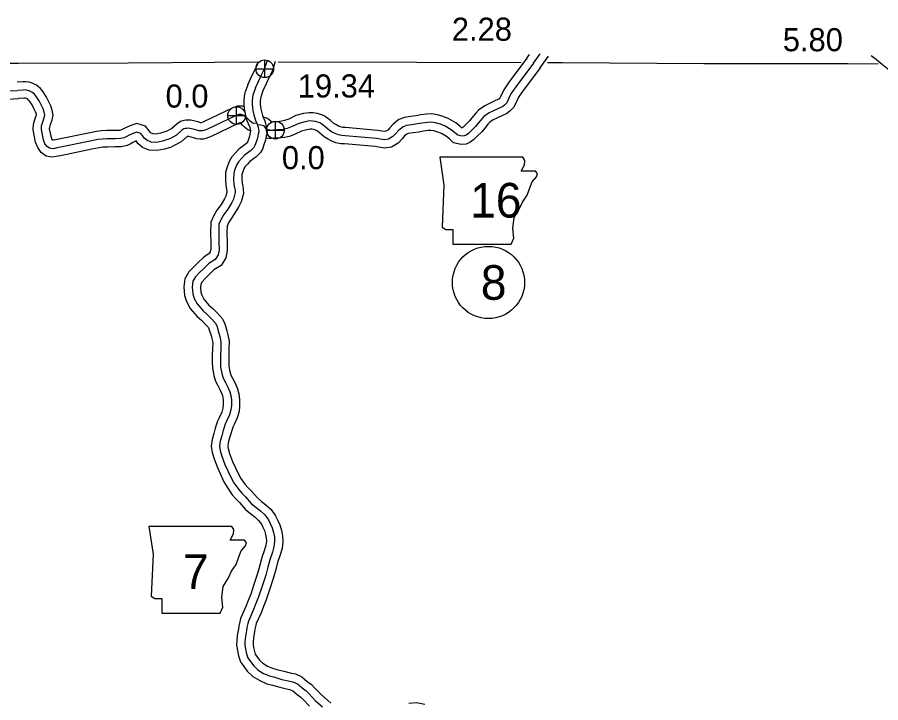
# Model space of a CAD drawing. Extents: x 31699 to 244310, y -8841 to 11474.
# Drawn here: x 96581 to 97635, y 8769 to 9604 of the extents above; entities that cross this region are included whole.
import ezdxf

# ---------------------------------------------------------------- set-up
doc = ezdxf.new("R2010")
doc.units = 0
for name, color, linetype in [('B_Logo', 7, 'Continuous'), ('G-ANNO-TEXT', 7, 'Continuous'), ('Level 21', 7, 'Continuous'), ('R_Border Notes', 7, 'Continuous'), ('R_Logo', 7, 'Continuous'), ('R_XS_EARTHWORK_STAGE2', 7, 'Continuous'), ('S_WALL_ANNOT', 7, 'Continuous')]:
    doc.layers.add(name, color=color, linetype=linetype)

msp = doc.modelspace()

# ---------------------------------------------------------------- linework, layer by layer
at = {"layer": 'B_Logo'}
for points in [[(97211.2, 9548.6), (97219.5, 9559.9)], [(96871.9, 9518.4), (96875.1, 9525.2), (96879.1, 9533.6), (96882.6, 9540.9), (96884.6, 9545.9), (96886.2, 9550.9), (96886.5, 9552)], [(97211.2, 9548.6), (97189.6, 9519.7), (97185.7, 9513.9), (97183.6, 9510.9), (97181.2, 9505.6), (97178.6, 9500.3), (97175.9, 9497.3), (97173.6, 9495.7), (97167.5, 9492.9), (97157, 9487.9), (97150.8, 9483.6), (97148.4, 9481), (97143.9, 9475.5), (97140.6, 9471.3), (97135.5, 9466.3), (97132.1, 9462.8), (97128.9, 9460.5), (97126.7, 9459.7), (97123.6, 9459.3), (97118.7, 9460.6), (97115.2, 9463.7), (97110.8, 9467.3), (97103.3, 9471.6), (97097.8, 9474), (97091.7, 9475.6), (97086.5, 9476.5), (97081.7, 9476.3), (97075.3, 9475.4), (97069.7, 9474.4), (97062.8, 9473.4), (97056.2, 9472.4), (97052, 9471), (97046.9, 9466.9), (97043.3, 9462.8), (97039.7, 9459), (97034.4, 9455.8), (97029.1, 9455), (97019.5, 9456.6), (96981.3, 9460), (96977.3, 9460.2), (96973.1, 9461.1), (96969.2, 9462.6), (96964.9, 9464.8), (96961.8, 9466.8), (96956.6, 9471.2), (96953, 9474.2), (96950.5, 9475.6), (96945.4, 9477.4), (96941.5, 9477.9), (96938.2, 9478), (96932.5, 9477.1), (96924.8, 9475.1), (96916.6, 9471.1), (96910.6, 9468.8), (96905.8, 9467.7), (96899, 9467.1), (96893.8, 9466.8), (96890.9, 9466.5), (96889.8, 9466.6), (96887.1, 9467), (96885.1, 9468.5), (96883.4, 9470.7), (96882, 9472), (96878.6, 9472.9), (96874.5, 9473.4)], [(96534.7, 9516.4), (96538.7, 9517.3), (96542.4, 9517.2), (96545.6, 9517.2), (96550.5, 9516.7), (96556.5, 9516.1), (96562.1, 9515.5), (96564.7, 9515.2), (96570.1, 9514.6), (96582, 9515.3)], [(96873.7, 9475.2), (96870.2, 9475), (96867.8, 9475.9), (96865.5, 9477.9), (96863, 9480.2), (96861.4, 9481.8), (96859.7, 9483.5), (96857.9, 9484.8), (96854.5, 9486), (96851.8, 9486), (96847.7, 9484.3), (96813.4, 9468.1), (96811.3, 9467.3), (96808.5, 9466.2), (96807.1, 9465.9), (96805, 9465.8), (96802.7, 9466.1), (96799.1, 9467.2), (96795.9, 9468.1), (96791.9, 9468.9), (96790, 9469.1), (96788.2, 9468.9), (96786.4, 9468.8), (96784.8, 9468.3), (96782.3, 9466.6), (96775.6, 9460.8), (96768.5, 9456.8), (96764.8, 9455.2), (96758.7, 9453.5), (96751.2, 9451.9), (96744.8, 9452.2), (96739.5, 9454.4), (96736.2, 9457.2), (96734.3, 9460.2), (96732, 9462.9), (96727.3, 9464.4), (96723.5, 9463.2), (96717.9, 9460.6), (96714.2, 9458.7), (96712, 9457.5), (96707.3, 9456.6), (96700.8, 9456.3), (96691, 9456.2), (96685.1, 9455.8), (96679.5, 9455.3), (96670.3, 9453.4), (96634.1, 9445.9), (96629.7, 9445.1), (96627.1, 9444.6), (96623.8, 9444.1), (96620.7, 9444.7), (96617.7, 9446.8), (96615.2, 9450.2), (96613.4, 9455), (96610.8, 9467.7), (96611.1, 9472.2), (96612.5, 9476.8), (96614.3, 9482), (96615, 9485.3), (96614.4, 9488.8), (96613, 9492.7), (96611, 9497), (96608, 9502.6), (96604.9, 9507.5), (96602.4, 9510.5), (96599.3, 9513.3), (96596.1, 9514.7), (96593.9, 9515.3), (96591.1, 9515.8), (96588.7, 9515.7), (96582, 9515.3)], [(96871.9, 9518.4), (96868.8, 9509.6), (96868.3, 9507), (96867.9, 9502.3), (96867.9, 9498.5), (96868.3, 9493.9), (96868.8, 9490.8), (96870, 9485.5), (96871.1, 9481.6), (96872.2, 9478.5), (96873.7, 9475.2), (96874.5, 9473.4), (96875.7, 9468.1), (96876.1, 9464.6), (96875.2, 9461.8), (96874.5, 9457), (96873.3, 9453.5), (96871.3, 9447.9), (96870.1, 9445.8), (96865.9, 9441.6), (96858.5, 9436.1), (96854.9, 9432.2), (96851.4, 9428.3), (96848.9, 9424.2), (96846.5, 9417.9), (96845.5, 9413.9), (96845.3, 9406.6), (96845.7, 9400.9), (96846.6, 9396.6), (96847.2, 9393.4), (96847.3, 9390.7), (96845.2, 9382.8), (96843.1, 9378.4), (96838.3, 9370.6), (96833.4, 9363.8), (96830.3, 9358.3), (96827.5, 9352.1), (96827.1, 9341.8), (96827.5, 9329.8), (96827.6, 9320.9), (96826.3, 9314.9), (96822.7, 9308.9), (96815.1, 9304.2), (96809, 9298.3), (96803.4, 9292.8), (96798.7, 9287.9), (96795.6, 9282.5), (96794.7, 9275.4), (96795.5, 9267.3), (96797.2, 9261.6), (96800.7, 9255.1), (96808.1, 9246.5), (96813.2, 9242), (96818.4, 9236.9), (96823.2, 9231.4), (96825.1, 9227), (96827.4, 9219.4), (96828.7, 9215.1), (96829.8, 9208.6), (96829.6, 9200.2), (96829.3, 9191.8), (96829.3, 9184.2), (96829.4, 9178), (96830.8, 9170.2), (96832.7, 9164.4), (96835, 9159.9), (96838, 9154.2), (96840.6, 9147.8), (96842.1, 9143.1), (96842.7, 9137.9), (96842.7, 9131.1), (96842.1, 9125.9), (96840.2, 9119.6), (96836.8, 9112.1), (96835.1, 9108.2), (96832.6, 9100.6), (96830.8, 9094.2), (96829, 9087.5), (96828, 9081.5), (96828.8, 9076.1), (96831.1, 9069.4), (96834.8, 9059.1), (96842.4, 9042.7), (96845.8, 9036.9), (96851.5, 9028.5), (96855.4, 9024.1), (96859.8, 9019.7), (96866.9, 9011.6), (96872.7, 9006.8), (96878.2, 9002.5), (96883.4, 8997.7), (96887.7, 8991.5), (96890, 8987.2), (96892.2, 8982), (96894.1, 8976.1), (96895.1, 8971), (96895.4, 8965.4), (96894.6, 8958.8), (96892.8, 8952.1), (96889.4, 8942.8), (96887.1, 8933.9)], [(96887.1, 8933.9), (96884.6, 8924.4), (96880, 8910.9), (96875.6, 8897.6), (96872.5, 8889.8), (96869.6, 8882.3), (96863.3, 8868.3), (96862.7, 8865.3), (96861.6, 8860.5), (96860.9, 8856.9), (96859.7, 8849.3), (96859.1, 8843), (96859, 8839.4), (96859.8, 8834), (96861, 8828.5), (96862.7, 8823.3), (96869.5, 8813.9), (96874.9, 8808.8), (96882, 8804.5), (96889.3, 8801.3), (96895.5, 8799.7), (96904.2, 8797.2), (96912, 8795.5), (96917.4, 8794.3), (96923.1, 8791.7), (96928.9, 8786.7), (96933.7, 8783.2), (96937.5, 8779.5), (96945, 8771.6), (96953.7, 8763.8)]]:
    msp.add_lwpolyline(points, dxfattribs=at)
at = {"layer": 'G-ANNO-TEXT'}
for points in [[(97097, 9433.7), (97102, 9399.9), (97099.8, 9348.6), (97104.3, 9345.7), (97112.7, 9345.7), (97112.7, 9327.7), (97183.8, 9327.7), (97187.2, 9335), (97186.1, 9346.9), (97187.8, 9360.4), (97194, 9371.1), (97197.9, 9379), (97203.5, 9387.5), (97206.9, 9396.5), (97209.7, 9403.8), (97214.8, 9410), (97215.9, 9414), (97213.7, 9416.8), (97196.2, 9416.8), (97200.2, 9424.7), (97200.7, 9429.8), (97198.4, 9433.7)], [(96741.9, 8983.7), (96747, 8949.8), (96744.7, 8898.5), (96749.2, 8895.7), (96757.7, 8895.7), (96757.7, 8877.7), (96828.8, 8877.7), (96832.1, 8885), (96831, 8896.8), (96832.7, 8910.4), (96838.9, 8921.1), (96842.9, 8929), (96848.5, 8937.4), (96851.9, 8946.5), (96854.7, 8953.8), (96859.8, 8960), (96860.9, 8963.9), (96858.6, 8966.8), (96841.2, 8966.8), (96845.1, 8974.7), (96845.7, 8979.7), (96843.3, 8983.6)]]:
    msp.add_lwpolyline(points, close=True, dxfattribs=at)
at = {"layer": 'Level 21'}
for p, q in [((96883.3, 9530.8), (96883.3, 9552.5)), ((96872.4, 9541.6), (96894.1, 9541.6)), ((96849, 9473.7), (96849, 9495.4)), ((96838.1, 9484.5), (96859.8, 9484.5)), ((96896.4, 9456), (96896.4, 9477.7)), ((96885.6, 9466.8), (96907.3, 9466.8))]:
    msp.add_line(p, q, dxfattribs=at)
for centre in [(96883.3, 9541.6), (96849, 9484.5), (96896.4, 9466.8)]:
    msp.add_circle(centre, 10.8, dxfattribs=at)
at = {"layer": 'R_Border Notes'}
msp.add_circle((97156.3, 9281.1), 44, dxfattribs=at)
at = {"layer": 'R_Logo'}
for points in [[(96089.4, 9556.1), (96192.5, 9555.3), (96361.7, 9545.8), (96371.2, 9545.5), (96540.1, 9548.2), (96548.3, 9548.3), (96582.7, 9548.4)], [(96582.7, 9548.4), (96716.8, 9548.7), (96875, 9550)], [(96899.7, 9550.2), (97069, 9549.5), (97196, 9549.4)], [(97228.3, 9549.3), (97246.7, 9549.3), (97419.1, 9548), (97594.6, 9548.2), (97596.3, 9547.8), (97631.7, 9547.9)]]:
    msp.add_lwpolyline(points, dxfattribs=at)
at = {"layer": 'R_XS_EARTHWORK_STAGE2'}
for points in [[(97203.1, 9554.6), (97206.3, 9558.9)], [(97219.2, 9542.7), (97229.7, 9556.9)], [(97623.2, 9558), (97629.2, 9553.3), (97632.6, 9550.6), (97637.1, 9546.7), (97641.2, 9543.5), (97645, 9540.4), (97647.4, 9538.3), (97649.1, 9536.1), (97652.1, 9531.9), (97655.6, 9527.1), (97660.4, 9522.8), (97664.6, 9519.3), (97668.5, 9517.1), (97674.4, 9514.4), (97678.7, 9513.2), (97683.7, 9511.8)], [(96862.6, 9522.2), (96866.1, 9529.5), (96870, 9537.9), (96873.5, 9544.9), (96875.1, 9549.2), (96875.6, 9550.6)], [(96881.1, 9514.6), (96884.2, 9520.9), (96888.1, 9529.2), (96891.8, 9536.9), (96894, 9542.5), (96895.7, 9547.9), (96896.6, 9550.8)], [(97203.1, 9554.6), (97181.5, 9525.5), (97177.4, 9519.5), (97174.9, 9515.8), (97172.2, 9509.8), (97170.3, 9506), (97169.2, 9504.8), (97168.6, 9504.4), (97163.3, 9502), (97152, 9496.6), (97144.3, 9491.2), (97140.8, 9487.6), (97136.1, 9481.7), (97133.1, 9478), (97128.4, 9473.4), (97125.5, 9470.4), (97124.2, 9469.5), (97123.5, 9469.7), (97121.7, 9471.3), (97116.5, 9475.6), (97107.8, 9480.6), (97101.1, 9483.4), (97093.9, 9485.4), (97087.2, 9486.5), (97080.7, 9486.3), (97073.7, 9485.3), (97068.1, 9484.3), (97061.3, 9483.3), (97053.9, 9482.1), (97047.1, 9479.9), (97039.9, 9474.2), (97035.9, 9469.5), (97033.4, 9466.8), (97031, 9465.4), (97029.2, 9465.2), (97020.7, 9466.5), (96982, 9469.9), (96978.7, 9470.1), (96975.9, 9470.8), (96973.2, 9471.7), (96969.9, 9473.5), (96967.8, 9474.8), (96963, 9478.8), (96958.8, 9482.4), (96954.8, 9484.7), (96947.7, 9487.2), (96942.3, 9487.9), (96937.5, 9488), (96930.4, 9486.9), (96921.3, 9484.5), (96912.6, 9480.3), (96907.6, 9478.4), (96904.2, 9477.6), (96898.3, 9477.1), (96893, 9476.8), (96891.5, 9476.7), (96890.7, 9477.7), (96886.8, 9481), (96881.7, 9482.5)], [(97219.2, 9542.7), (97197.8, 9513.9), (97193.9, 9508.2), (97192.4, 9506), (97190.3, 9501.3), (97187, 9494.5), (97182.5, 9489.8), (97178.7, 9487), (97171.7, 9483.8), (97162.1, 9479.3), (97157.4, 9476), (97155.9, 9474.4), (97151.7, 9469.3), (97148, 9464.6), (97142.6, 9459.3), (97138.6, 9455.2), (97133.7, 9451.6), (97129.1, 9449.9), (97122.9, 9449.2), (97113.8, 9451.5), (97108.6, 9456.1), (97105.1, 9459.1), (97098.8, 9462.7), (97094.5, 9464.5), (97089.6, 9465.9), (97085.9, 9466.5), (97082.6, 9466.4), (97076.9, 9465.5), (97071.3, 9464.5), (97064.3, 9463.5), (97058.5, 9462.6), (97056.8, 9462), (97053.9, 9459.7), (97050.8, 9456.1), (97046.1, 9451.1), (97037.8, 9446.1), (97029, 9444.9), (97018.2, 9446.7), (96980.6, 9450), (96976, 9450.3), (96970.2, 9451.5), (96965.2, 9453.4), (96959.9, 9456.1), (96955.9, 9458.7), (96950.2, 9463.5), (96947.2, 9466), (96946.3, 9466.5), (96943.1, 9467.7), (96940.8, 9467.9), (96938.9, 9468), (96934.6, 9467.3), (96928.3, 9465.6), (96920.5, 9461.9), (96913.5, 9459.2), (96907.4, 9457.8), (96899.7, 9457.1), (96894.6, 9456.9), (96891.1, 9456.5), (96888.9, 9456.6), (96885.8, 9457.1)], [(96858.2, 9495.3), (96856.2, 9496), (96849.8, 9496), (96843.7, 9493.5), (96809.6, 9477.3), (96807.8, 9476.7), (96805.7, 9475.8), (96805.6, 9475.8), (96804.8, 9475.9), (96801.9, 9476.9), (96798.2, 9477.8), (96793.3, 9478.9), (96789.9, 9479.1), (96787.4, 9478.9), (96784.5, 9478.6), (96780.6, 9477.4), (96776.3, 9474.6), (96769.8, 9469), (96764, 9465.7), (96761.4, 9464.6), (96756.3, 9463.2), (96750.4, 9461.9), (96747, 9462.1), (96744.7, 9463.1), (96743.8, 9463.8), (96742.4, 9466.1), (96737.8, 9471.5), (96727.4, 9474.9), (96719.9, 9472.6), (96713.5, 9469.6), (96709.5, 9467.5), (96708.5, 9467), (96706.2, 9466.5), (96700.5, 9466.3), (96690.7, 9466.2), (96684.2, 9465.8), (96678, 9465.1), (96668.3, 9463.2), (96632.2, 9455.7), (96628, 9454.9), (96625.5, 9454.5), (96624.5, 9454.4), (96624.1, 9455), (96623, 9457.8), (96620.8, 9468.4), (96621, 9470.4), (96622, 9473.7), (96623.9, 9479.3), (96625.1, 9485.1), (96624.1, 9491.3), (96622.3, 9496.5), (96620, 9501.4), (96616.7, 9507.7), (96613, 9513.4), (96609.6, 9517.5), (96604.8, 9521.7), (96599.6, 9524.1), (96596.1, 9525.1), (96591.8, 9525.9), (96588.2, 9525.7), (96581.4, 9525.3)], [(96862.6, 9522.2), (96859.2, 9512.3), (96858.3, 9508.4), (96857.9, 9502.7), (96857.9, 9498.1), (96858.3, 9492.6), (96859, 9488.8), (96860.3, 9483.1), (96861.6, 9478.7), (96862.9, 9474.8), (96864.6, 9471.1), (96865, 9470.2), (96865.9, 9466.4), (96866, 9465.6), (96865.5, 9464), (96864.7, 9459.4), (96863.9, 9456.7), (96862.2, 9452), (96862.1, 9451.9), (96859.3, 9449.2), (96851.9, 9443.6), (96847.5, 9439), (96843.3, 9434.3), (96839.9, 9428.6), (96836.9, 9420.9), (96835.5, 9415.3), (96835.3, 9406.4), (96835.8, 9399.5), (96836.8, 9394.7), (96837.2, 9392.2), (96837.2, 9391.7), (96835.8, 9386.3), (96834.3, 9383.2), (96830, 9376.1), (96824.9, 9369.2), (96821.4, 9362.8), (96817.5, 9354.5), (96817.1, 9341.8), (96817.5, 9329.6), (96817.6, 9321.9), (96816.9, 9318.6), (96815.4, 9316.2), (96808.9, 9312.1), (96802, 9305.5), (96796.2, 9299.8), (96790.6, 9293.9), (96786, 9285.7), (96784.6, 9275.6), (96785.6, 9265.3), (96787.9, 9257.8), (96792.4, 9249.4), (96800.9, 9239.4), (96806.4, 9234.6), (96811.2, 9230), (96814.6, 9226), (96815.7, 9223.5), (96817.8, 9216.6), (96818.9, 9212.9), (96819.8, 9207.8), (96819.6, 9200.5), (96819.3, 9192), (96819.3, 9184.1), (96819.4, 9176.9), (96821.1, 9167.8), (96823.4, 9160.6), (96826.1, 9155.3), (96828.9, 9149.9), (96831.2, 9144.4), (96832.3, 9141), (96832.7, 9137.4), (96832.7, 9131.7), (96832.3, 9127.8), (96830.8, 9123.1), (96827.7, 9116.2), (96825.7, 9111.8), (96823, 9103.5), (96821.1, 9096.9), (96819.2, 9089.6), (96817.9, 9081.6), (96819, 9073.8), (96821.7, 9066.1), (96825.6, 9055.3), (96833.6, 9038.1), (96837.4, 9031.6), (96843.6, 9022.3), (96848.2, 9017.2), (96852.5, 9012.9), (96859.9, 9004.4), (96866.5, 8999), (96871.7, 8994.9), (96875.9, 8991), (96879.2, 8986.3), (96881, 8982.9), (96882.9, 8978.5), (96884.4, 8973.6), (96885.1, 8969.8), (96885.3, 8965.8), (96884.8, 8960.7), (96883.2, 8955.2), (96879.9, 8945.7), (96877.4, 8936.4)], [(96881.1, 9514.6), (96878.5, 9506.9), (96878.2, 9505.5), (96877.9, 9501.9), (96877.9, 9498.9), (96878.2, 9495.2), (96878.6, 9492.8), (96879.7, 9488), (96880.7, 9484.5), (96881.5, 9482.2), (96882.9, 9479.2), (96884, 9476.5), (96885.6, 9469.8), (96886.3, 9463.6), (96885, 9459.5), (96884.2, 9454.7), (96882.8, 9450.2), (96880.5, 9443.8), (96878.2, 9439.6), (96872.4, 9434), (96865.2, 9428.6), (96862.2, 9425.4), (96859.4, 9422.4), (96857.9, 9419.8), (96856, 9414.9), (96855.4, 9412.5), (96855.3, 9406.9), (96855.7, 9402.3), (96856.4, 9398.4), (96857.1, 9394.6), (96857.4, 9389.7), (96854.6, 9379.3), (96851.9, 9373.6), (96846.6, 9365), (96841.8, 9358.4), (96839.2, 9353.7), (96837.4, 9349.7), (96837.1, 9341.8), (96837.5, 9330), (96837.6, 9320), (96835.8, 9311.1), (96830, 9301.7), (96821.3, 9296.3), (96816, 9291.1), (96810.5, 9285.8), (96806.8, 9281.8), (96805.3, 9279.2), (96804.8, 9275.2), (96805.3, 9269.2), (96806.5, 9265.5), (96809, 9260.8), (96815.2, 9253.5), (96820, 9249.3), (96825.7, 9243.8), (96831.7, 9236.8), (96834.5, 9230.5), (96837, 9222.3), (96838.4, 9217.4), (96839.8, 9209.4), (96839.6, 9199.9), (96839.3, 9191.6), (96839.3, 9184.2), (96839.4, 9179), (96840.6, 9172.7), (96842, 9168.2), (96843.9, 9164.5), (96847.1, 9158.4), (96850, 9151.2), (96851.9, 9145.2), (96852.7, 9138.4), (96852.6, 9130.6), (96852, 9123.9), (96849.6, 9116), (96845.9, 9108), (96844.4, 9104.6), (96842.2, 9097.7), (96840.4, 9091.5), (96838.8, 9085.5), (96838.1, 9081.4), (96838.5, 9078.5), (96840.5, 9072.7), (96844.1, 9062.9), (96851.3, 9047.3), (96854.3, 9042.2), (96859.4, 9034.7), (96862.7, 9031), (96867.1, 9026.5), (96873.9, 9018.8), (96879, 9014.6), (96884.7, 9010.1), (96891, 9004.3), (96896.3, 8996.7), (96899, 8991.5), (96901.6, 8985.5), (96903.8, 8978.6), (96905.1, 8972.2), (96905.4, 8965.1), (96904.5, 8956.9), (96902.3, 8949.1), (96899, 8939.8), (96896.7, 8931.3)], [(96537, 9506.7), (96539.7, 9507.3), (96542.2, 9507.2), (96545, 9507.2), (96549.5, 9506.7), (96555.5, 9506.2), (96560.9, 9505.6), (96563.5, 9505.3), (96569.9, 9504.5), (96582.7, 9505.4)], [(96866, 9465.9), (96862.6, 9467.2), (96858.7, 9470.5), (96856.1, 9473), (96854.4, 9474.7), (96853.3, 9475.8), (96851.8, 9475.2), (96817.3, 9458.8), (96814.8, 9457.9), (96811.6, 9456.7), (96808.4, 9455.9), (96804.3, 9455.8), (96800.5, 9456.3), (96796.4, 9457.6), (96793.5, 9458.3), (96790.5, 9459), (96790.1, 9459), (96789.1, 9458.9), (96788.8, 9458.9), (96788.3, 9458.6), (96781.4, 9452.6), (96773, 9447.9), (96768.2, 9445.7), (96761.1, 9443.8), (96752, 9441.8), (96742.5, 9442.3), (96734.3, 9445.7), (96728.5, 9450.5), (96726.6, 9453.6), (96722.3, 9451.7), (96719, 9449.9), (96715.4, 9448), (96708.5, 9446.6), (96701, 9446.3), (96691.4, 9446.2), (96685.9, 9445.9), (96681.1, 9445.4), (96672.3, 9443.6), (96636, 9436), (96631.3, 9435.2), (96628.7, 9434.8), (96623.7, 9434), (96616.8, 9435.2), (96610.6, 9439.6), (96606.3, 9445.5), (96603.7, 9452.3), (96600.7, 9467), (96601.1, 9474), (96603, 9479.9), (96604.6, 9484.7), (96604.8, 9485.6), (96604.7, 9486.3), (96603.7, 9489), (96602.1, 9492.5), (96599.4, 9497.6), (96596.8, 9501.6), (96595.2, 9503.5), (96593.8, 9504.8), (96592.7, 9505.3), (96591.6, 9505.6), (96590.4, 9505.8), (96589.2, 9505.8), (96582.6, 9505.3)], [(96877.4, 8936.4), (96875, 8927.3), (96870.5, 8914.1), (96866.2, 8901), (96863.2, 8893.5), (96860.4, 8886.1), (96853.7, 8871.4), (96852.9, 8867.4), (96851.8, 8862.5), (96851.1, 8858.7), (96849.7, 8850.5), (96849.1, 8843.6), (96848.9, 8838.9), (96849.9, 8832.2), (96851.4, 8825.8), (96853.7, 8818.7), (96861.9, 8807.3), (96868.8, 8800.8), (96877.4, 8795.6), (96886, 8791.9), (96892.9, 8790), (96901.8, 8787.5), (96909.8, 8785.8), (96914.1, 8784.8), (96917.7, 8783.1), (96922.7, 8778.9), (96927.2, 8775.6), (96930.3, 8772.5), (96938, 8764.4)], [(96896.7, 8931.3), (96894.2, 8921.5), (96889.5, 8907.7), (96885, 8894.2), (96881.8, 8886.2), (96878.8, 8878.4), (96872.9, 8865.2), (96872.4, 8863.2), (96871.4, 8858.4), (96870.7, 8855.2), (96869.6, 8848.1), (96869.1, 8842.3), (96869, 8839.9), (96869.6, 8835.9), (96870.7, 8831.2), (96871.7, 8827.9), (96877.1, 8820.5), (96881, 8816.8), (96886.6, 8813.4), (96892.6, 8810.8), (96898.1, 8809.3), (96906.7, 8807), (96914.3, 8805.3), (96920.7, 8803.8), (96928.5, 8800.2), (96935.1, 8794.6), (96940.2, 8790.9), (96944.6, 8786.5), (96952, 8778.7), (96960.1, 8771.4), (96964.1, 8768.3)], [(97059.2, 8768.1), (97068.6, 8769.1), (97078.8, 8767.1)]]:
    msp.add_lwpolyline(points, dxfattribs=at)

# ---------------------------------------------------------------- texts
at = {"layer": 'G-ANNO-TEXT'}
for s, height, p in [('16', 42.24, (97133.8, 9360.2)), ('7', 42.2, (96783.5, 8907.5))]:
    msp.add_text(s, height=height, dxfattribs=at).set_placement(p)
at = {"layer": 'R_Border Notes'}
msp.add_text('8', height=42.2, dxfattribs=at).set_placement((97146.9, 9260))
at = {"layer": 'S_WALL_ANNOT'}
for s, p in [('2.28', (97111.6, 9575.8)), ('5.80', (97515.4, 9563)), ('19.34', (96923.6, 9506.6)), ('0.0', (96762.3, 9494.3)), ('0.0', (96904.2, 9419.2))]:
    msp.add_text(s, height=28.16, dxfattribs=at).set_placement(p)

doc.saveas('drawing.dxf')
